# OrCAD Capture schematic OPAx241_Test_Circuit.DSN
size A; title: OPAx241, Single-Supply, MicroPOWER OPERATIONAL AMPLIFIERS; rev: 1.1; note: Datasheet: SBOS075   EVM: N/A
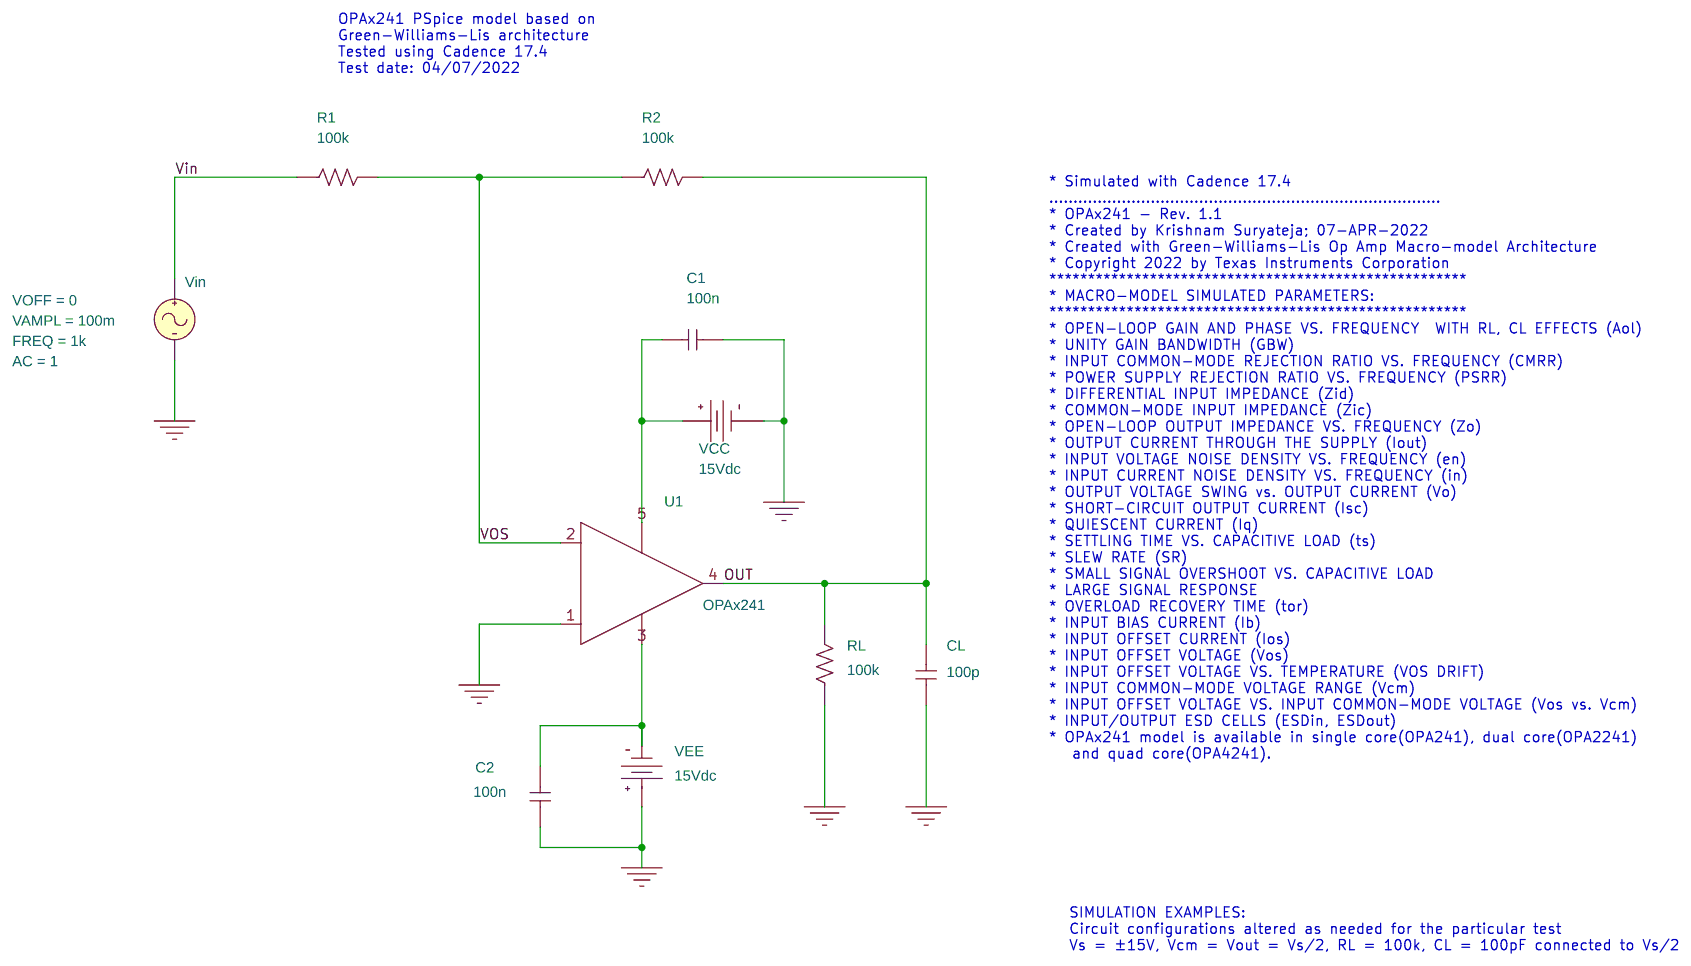
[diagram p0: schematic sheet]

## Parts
C1  100n  [cap196]
C2  100n  [cap196]
CL  100p  [cap196]
R1  100k  [AXRC05]
R2  100k  [AXRC05]
RL  100k  [AXRC05]
U1  OPAx241
VCC  VDC
VEE  VDC
Vin  VSIN

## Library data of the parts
C1 C2 CL = C
R1 R2 RL = R
U1 = OPAx241
VCC VEE = VDC: DC: 15Vdc
Vin = VSIN: AC: 1; FREQ: 1k; VAMPL: 100m; VOFF: 0

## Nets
Vin: R1.1 Vin.1(+)
0: C1.2 C2.1 CL.2 RL.1 U1.1(+) VCC.1(-) VEE.0(+) Vin.2(-)
OUT: CL.1 R2.2 RL.2 U1.4(OUT)
VOS: R1.2 R2.1 U1.2(-)
N27303: C1.1 U1.5(V+) VCC.0(+)
N27354: C2.2 U1.3(V-) VEE.1(-)

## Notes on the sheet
- OPAx241 PSpice model based on
  Green-Williams-Lis architecture
  Tested using Cadence 17.4
  Test date: 04/07/2022
- * Simulated with Cadence 17.4
  .................................................................................
  * OPAx241 - Rev. 1.1
  * Created by Krishnam Suryateja; 07-APR-2022
  * Created with Green-Williams-Lis Op Amp Macro-model Architecture
  * Copyright 2022 by Texas Instruments Corporation
  ******************************************************
  * MACRO-MODEL SIMULATED PARAMETERS:
  ******************************************************
  * OPEN-LOOP GAIN AND PHASE VS. FREQUENCY  WITH RL, CL EFFECTS (Aol)
  * UNITY GAIN BANDWIDTH (GBW)
  * INPUT COMMON-MODE REJECTION RATIO VS. FREQUENCY (CMRR)
  * POWER SUPPLY REJECTION RATIO VS. FREQUENCY (PSRR)
  * DIFFERENTIAL INPUT IMPEDANCE (Zid)
  * COMMON-MODE INPUT IMPEDANCE (Zic)
  * OPEN-LOOP OUTPUT IMPEDANCE VS. FREQUENCY (Zo)
  * OUTPUT CURRENT THROUGH THE SUPPLY (Iout)
  * INPUT VOLTAGE NOISE DENSITY VS. FREQUENCY (en)
  * INPUT CURRENT NOISE DENSITY VS. FREQUENCY (in)
  * OUTPUT VOLTAGE SWING vs. OUTPUT CURRENT (Vo)
  * SHORT-CIRCUIT OUTPUT CURRENT (Isc)
  * QUIESCENT CURRENT (Iq)
  * SETTLING TIME VS. CAPACITIVE LOAD (ts)
  * SLEW RATE (SR)
  * SMALL SIGNAL OVERSHOOT VS. CAPACITIVE LOAD
  * LARGE SIGNAL RESPONSE
  * OVERLOAD RECOVERY TIME (tor)
  * INPUT BIAS CURRENT (Ib)
  * INPUT OFFSET CURRENT (Ios)
  * INPUT OFFSET VOLTAGE (Vos)
  * INPUT OFFSET VOLTAGE VS. TEMPERATURE (VOS DRIFT)
  * INPUT COMMON-MODE VOLTAGE RANGE (Vcm)
  * INPUT OFFSET VOLTAGE VS. INPUT COMMON-MODE VOLTAGE (Vos vs. Vcm)
  * INPUT/OUTPUT ESD CELLS (ESDin, ESDout)
  * OPAx241 model is available in single core(OPA241), dual core(OPA2241)
     and quad core(OPA4241).
- SIMULATION EXAMPLES:
  Circuit configurations altered as needed for the particular test
  Vs = ±15V, Vcm = Vout = Vs/2, RL = 100k, CL = 100pF connected to Vs/2
